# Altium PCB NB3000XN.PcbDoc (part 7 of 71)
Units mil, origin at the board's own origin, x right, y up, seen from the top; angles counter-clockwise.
Board outline 9527.56 x 6929.77 mil, 6 copper layers (Top Layer, GND+SHIELD, MidLayer1, MidLayer2, P2 - 3V3+5V0, Bottom Layer), stack 62.375 mil thick; 832 components, 1027 nets, 4655 pads, 4981 vias.
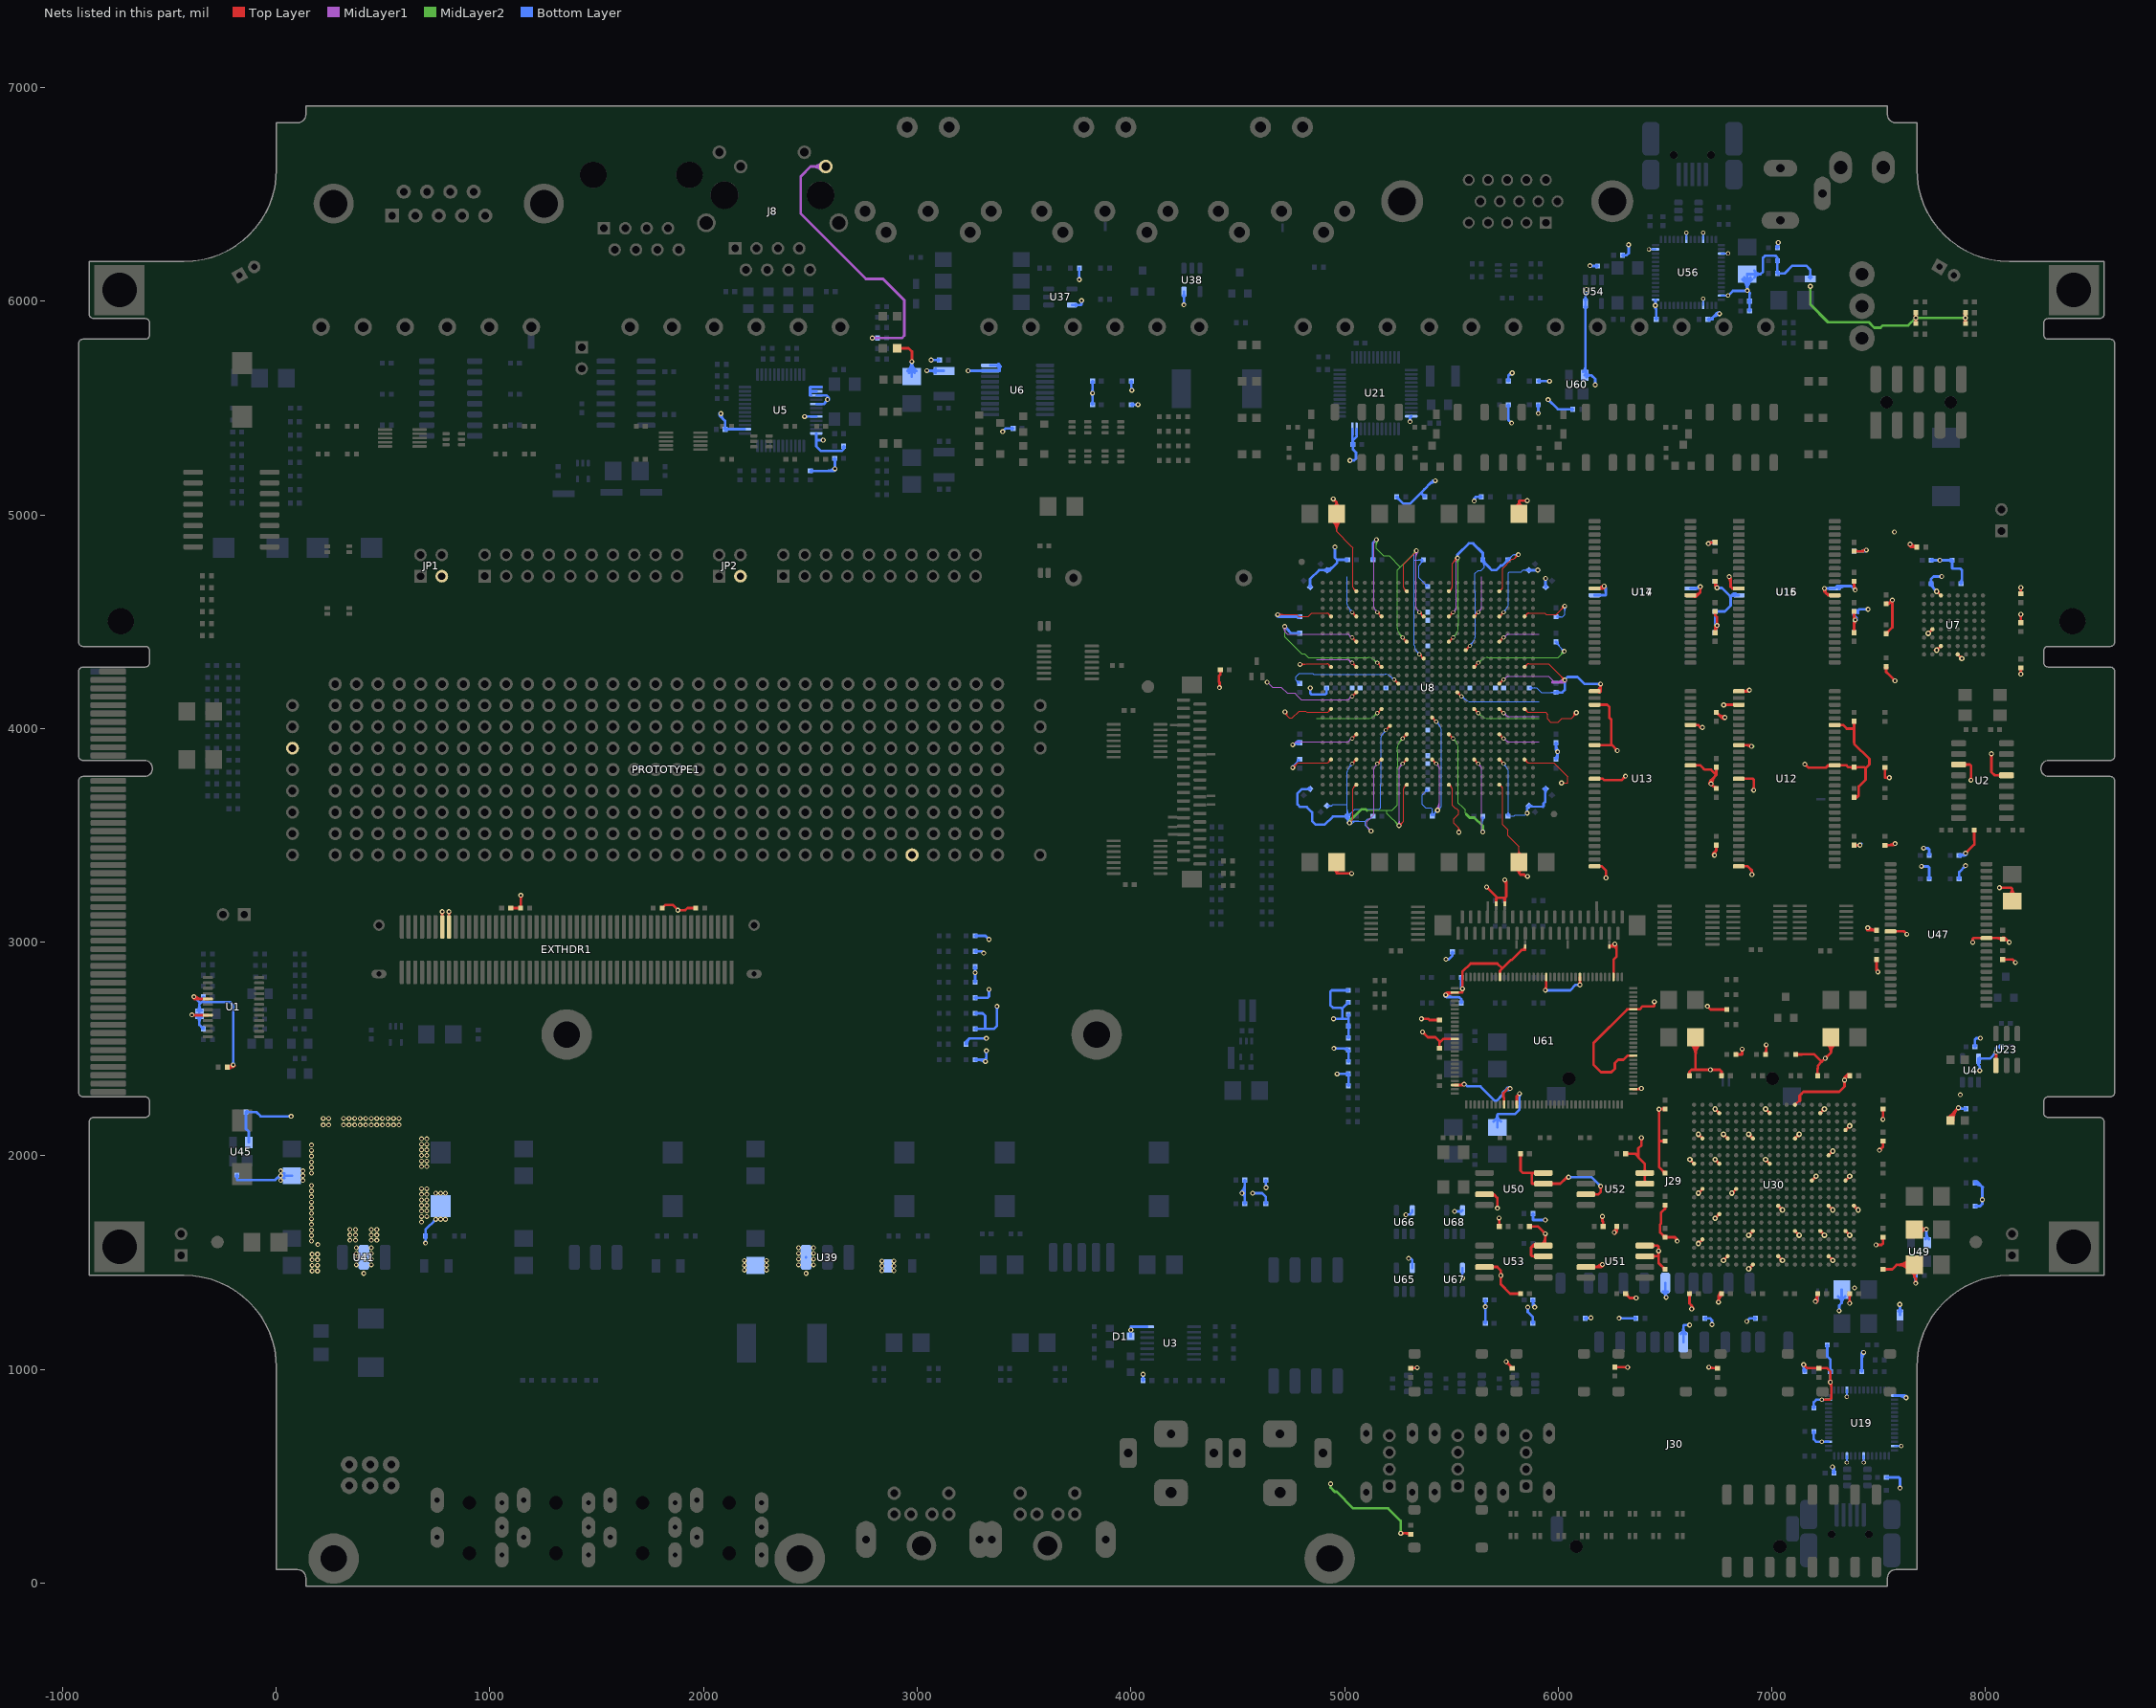
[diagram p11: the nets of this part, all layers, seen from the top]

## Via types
v1: diameter 23, hole 11.81, Top Layer to Bottom Layer, 3672 vias
v2: diameter 26, hole 11.81, Top Layer to Bottom Layer, 461 vias
v3: diameter 19, hole 11.81, Top Layer to Bottom Layer, tented both sides, 396 vias
v4: diameter 23.62, hole 11.81, Top Layer to Bottom Layer, 288 vias
v5: diameter 20, hole 11.81, Top Layer to Bottom Layer, 91 vias
v6: diameter 23, hole 11.81, Top Layer to Bottom Layer, tented both sides, 50 vias
v7: diameter 31, hole 11.81, Top Layer to Bottom Layer, 15 vias
v8: diameter 27.56, hole 11.81, Top Layer to Bottom Layer, tented both sides, 4 vias
v9: diameter 29, hole 11.81, Top Layer to Bottom Layer, 3 vias
v10: diameter 21, hole 11.81, Top Layer to Bottom Layer, 1 vias

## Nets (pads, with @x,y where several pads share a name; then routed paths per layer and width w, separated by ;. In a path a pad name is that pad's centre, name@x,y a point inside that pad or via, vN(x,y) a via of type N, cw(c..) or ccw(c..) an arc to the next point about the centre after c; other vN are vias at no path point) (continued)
3V3: (continued)
  Top Layer w12: v4(-395,2660) -393.62,2658.62 U1.8@-320,2658.62 ; v4@-390.89,2664.11 ccw(c-377.64,2677.36) -377.64,2658.62 ; v1@-389.6,2740.4 ccw(c-374.65,2755.35) -374.65,2734.21 ; v1(-385,2745) -385,2736.23 -382.98,2734.21 U1.5@-320,2734.21 ; v1@-381.11,2748.89 ccw(c-345.68,2784.32) -345.68,2734.21 ; R99.2@-231.27,2409.28 ccw(c-225.51,2423.88) -214.41,2412.78 ; R99.2@-226.86,2420.44 ccw(c-218.18,2442.41) v1(-201.48,2425.71) -212.18,2415 R99.2@-228.82,2415 ccw(c-228.82,2440.67) v1@-206.3,2428.35 ; R99.2@-225.06,2411.24 cw(c-215.98,2402.16) -215.98,2415 cw(c-215.98,2427.84) R99.2@-225.06,2418.76 ; -208.57,2415 ccw(c-208.57,2429.59) v1@-195.77,2422.59 ; v1@772.94,3139.15 cw(c763.18,3129.38) 776.99,3129.38 ; EXTHDR1.87@776.99,3071.85 v1@776.99,3142.88 ; 776.99,3130.14 cw(c789.73,3130.14) v1@780.72,3139.15 ; v1@804.44,3139.15 cw(c794.67,3129.38) 808.49,3129.38 ; EXTHDR1.85@808.49,3071.85 v1@808.49,3142.88 ; 808.49,3130.14 cw(c821.23,3130.14) v1@812.22,3139.15 ; R283.1@1097.74,3160 R234.2@1143.82,3160 1145,3161.18 v1(1145,3220) ; R283.1@1101.51,3156.24 cw(c1110.59,3147.15) 1110.59,3160 cw(c1110.58,3172.83) R283.1@1101.51,3163.76 ; R234.2@1140.06,3156.24 ccw(c1130.98,3147.16) 1130.98,3160 ccw(c1130.98,3172.84) R234.2@1140.06,3163.76 ; v1@1141.11,3216.11 cw(c1131.72,3206.72) 1145,3206.72 cw(c1158.28,3206.72) v1@1148.89,3216.11 ; R277.1@1806.34,3160.02 1821.32,3175 1855.06,3175 v1(1880.02,3150.04) 1915.04,3150.04 1925.03,3160.03 R278.2@1964.34,3160.03 ; LED3.1@2905,5780 2960,5780 2975.19,5764.81 v1(2975.19,5717.71) ; LED3.1@2914.82,5770.47 cw(c2937.36,5748.59) 2937.36,5780 cw(c2937.36,5811.41) LED3.1@2914.82,5789.53 ; v1@2971.3,5721.6 ccw(c2961.91,5730.99) 2975.19,5730.99 ccw(c2988.47,5730.99) v1@2979.08,5721.6 ; v1@4411.3,4195.6 ccw(c4401.91,4204.99) 4415.19,4204.99 ccw(c4428.47,4204.99) v1@4419.08,4195.6 ; v1@4412.02,4194.87 v1(4415.19,4191.71) 4415.19,4216.83 4412.02,4220 4412.02,4245 4418.82,4251.79 R147.1@4418.82,4275 ; R147.1@4415.06,4270.75 cw(c4405.98,4261.67) 4418.82,4261.67 cw(c4431.66,4261.67) R147.1@4422.58,4270.75 ; v1(4947.19,5075.04) 4947.19,5068.37 4948.86,5066.71 4955.52,5066.71 4962.99,5059.24 ; C276.1@4950.02,5039.68 ccw(c4941.77,5059.24) 4962.99,5059.24 ; C278.1@4951.56,3339.71 cw(c4945.6,3323.38) 4962.99,3323.38 ; C278.1@4962.99,3375 4962.99,3323.37 ; C276.1@4962.99,4982.01 C276.1@4962.99,5005 4962.99,5059.24 ; C278.1@4974.42,3339.71 ccw(c4980.38,3323.38) 4962.99,3323.38 ; C276.1@4975.97,5039.68 cw(c4984.22,5059.24) 4962.99,5059.24 ; v1@5029.64,3317.82 ccw(c5020.25,3308.43) 5020.25,3321.71 ccw(c5020.25,3334.99) v1@5029.64,3325.6 ; v1(5033.52,3321.71) 4964.66,3321.71 4962.99,3323.37 ; v1@5266.75,229.49 cw(c5276.14,220.1) 5276.14,233.37 cw(c5276.14,246.65) v1@5266.75,237.26 ; v1@5267.41,228.82 v1(5262.86,233.37) 5305.44,233.37 R107.1@5310,228.82 ; 5285.67,233.37 cw(c5285.67,204.98) R107.1@5305.75,225.06 ; R102.1@5310,1006.18 5338.19,1006.18 5340.19,1008.18 v1(5340.19,1008.37) ; R102.1@5314.25,1002.42 cw(c5323.33,993.34) 5323.33,1006.18 cw(c5323.33,1019.02) R102.1@5314.25,1009.94 ; R102.1@5321.62,1006.18 ccw(c5321.62,1026.95) v1@5336.3,1012.26 ; v1@5360.19,2641.85 5392.19,2641.85 5397.86,2636.18 R273.2@5445,2636.18 ; v1@5364.08,2637.82 cw(c5373.8,2628.09) 5373.8,2641.85 ; v1@5364.08,2645.6 ccw(c5373.13,2654.65) 5373.13,2641.85 ; v4@5365,2574.19 cw(c5365,2560.16) 5374.92,2570.08 cw(c5384.84,2580) v4@5370.81,2580 ; v4(5365,2580) 5389.88,2555.12 5425.12,2555.12 5445,2535.23 ; R273.2@5440.75,2632.42 ccw(c5431.67,2623.34) 5431.67,2636.18 ccw(c5431.67,2649.02) R273.2@5440.75,2639.94 ; R272.2@5441.24,2507.45 ccw(c5432.16,2516.53) 5445,2516.53 ccw(c5457.84,2516.53) R272.2@5448.76,2507.45 ; R272.2@5445,2503.69 5445,2535.23 ; v1@5469.26,2757.3 cw(c5487.14,2739.43) 5487.14,2764.71 ; v1(5473.86,2752.71) 5485.86,2764.71 U61.104@5516.83,2764.71 ; v1@5477.75,2748.82 cw(c5516.11,2710.46) U61.104@5516.11,2764.71 ; U61.126@5516.83,2331.35 5554.88,2331.35 v1@5560,2336.47 ; U61.115@5516.83,2547.88 5463.03,2547.88 5447.69,2532.54 5445,2535.23 ; 5537.9,2331.35 ccw(c5537.9,2357.1) v1@5556.11,2338.89 ; v1@5547.97,2785.93 ccw(c5538.58,2795.32) 5551.86,2795.32 ccw(c5565.14,2795.32) v1@5555.75,2785.93 ; v1(5560,2335) v1@5560,2336.47 ; v1@5560,2340 v1@5560,2336.47 ; U53.3@5655,1480 5715.19,1480 5731.86,1463.33 v1(5731.86,1440.19) 5731.86,1398.62 5775.48,1355 C165.2@5824.33,1355 ; U50.3@5655,1820 5698.52,1820 ; v1@5665.19,3252.87 cw(c5665.19,3239.6) 5674.58,3248.99 cw(c5683.97,3258.37) v1@5670.69,3258.37 ; v1(5665.19,3258.37) 5715.19,3208.37 ; U50.3@5684.53,1824.22 cw(c5684.53,1800.62) 5701.22,1817.31 ; U50.3@5689.37,1813.91 cw(c5696.94,1804.42) 5705.52,1813 ; U53.3@5690.03,1474.5 cw(c5703.31,1461.22) 5703.31,1480 cw(c5703.31,1498.78) U53.3@5690.03,1485.5 ; U50.3@5691.13,1815.89 cw(c5698.52,1811.3) 5698.52,1820 ; U50.3@5691.13,1824.11 ccw(c5698.52,1828.7) 5698.52,1820 ; NT36.2@5710,3180 5710,3203.52 5714.86,3208.37 5715.19,3208.37 ; v1@5711.3,1758.93 ccw(c5701.91,1768.32) 5715.19,1768.32 ccw(c5728.47,1768.32) v1@5719.08,1758.93 ; v1(5715.19,1755.04) 5715.19,1803.33 5698.52,1820 ; v1@5719.64,1705.15 cw(c5708.3,1693.81) 5724.33,1693.81 ; C158.1@5720.22,1674.11 ccw(c5710.3,1684.03) 5724.33,1684.03 ccw(c5738.36,1684.03) C158.1@5728.44,1674.11 ; C158.1@5724.33,1670 v1@5724.33,1709.04 ; U61.94@5727.48,2837.34 5727.48,2866.71 ; 5727.52,2866.71 5738.02,2877.21 ; v1@5727.97,1436.3 cw(c5718.58,1426.92) 5731.86,1426.92 cw(c5745.14,1426.92) v1@5735.75,1436.3 ; v1@5727.97,1444.08 ccw(c5718.58,1453.47) 5731.86,1453.47 ccw(c5745.14,1453.47) v1@5735.75,1444.08 ; v1@5746.3,3287.82 cw(c5720.82,3262.33) 5756.86,3262.33 ; U61.10@5747.17,2240 5747.17,2271.33 5743.5,2275 5743.5,2293.91 5764.97,2315.37 5779.52,2315.37 5779.15,2315 v1(5775,2315) ; NT35.2@5750,3180 5750,3207.18 ; v1(5750.19,3291.71) 5756.86,3285.04 5756.86,3214.04 5750,3207.18 ; v1@5756.5,1031.16 cw(c5756.5,1017.88) 5765.89,1027.27 cw(c5775.28,1036.66) v1@5762,1036.66 ; v1(5756.5,1036.66) 5785,1008.16 R103.1@5785,1006.18 ; 5773.68,1019.48 cw(c5760.38,1006.18) R103.1@5779.19,1006.18 ; C277.1@5801.08,5038.26 ccw(c5786.53,5065.04) 5817.01,5065.04 ; C279.1@5805.37,3339.79 cw(c5799.14,3323.04) 5817.01,3323.04 ; U61.13@5806.22,2240 5806.22,2278.74 v1(5819.19,2291.71) ; C279.1@5817.01,3375 5817.01,3323.04 ; C277.1@5817.01,5005 5817.01,5065.04 ; C165.2@5820.22,1350.89 ccw(c5810.3,1340.97) 5810.3,1355 ccw(c5810.3,1369.03) C165.2@5820.22,1359.11 ; C159.2@5820.22,2005.89 cw(c5810.3,1995.97) 5824.33,1995.97 cw(c5838.36,1995.97) C159.2@5828.44,2005.89 ; C159.2@5824.33,2010 5824.33,1930.67 5835,1920 5874.19,1920 ; C279.1@5828.64,3339.79 ccw(c5834.88,3323.04) 5817.01,3323.04 ; C277.1@5832.94,5038.26 cw(c5847.48,5065.04) 5817.01,5065.04 ; NT37.2@5845,2975.5 cw(c5828.52,2980.84) 5828.52,2963.52 ; NT37.2@5845,2980 5845,2965 5843.52,2963.52 5828.52,2963.52 ; v1@5848.52,3308.37 5840.52,3316.37 5823.67,3316.37 5817.01,3323.04 ; v1@5851.3,5062.82 ccw(c5841.91,5053.43) 5841.91,5066.71 ccw(c5841.91,5079.99) v1@5851.3,5070.6 ; v1(5855.19,5066.71) 5818.67,5066.71 5817.01,5065.04 ; C164.1@5865.67,1670 5905.19,1670 v1(5940,1635.19) v1@5940,1630.04 ; C164.1@5869.78,1665.89 cw(c5879.7,1655.97) 5879.7,1670 cw(c5879.7,1684.03) C164.1@5869.78,1674.11 ; 5872.25,1570.4 cw(c5886.52,1556.13) U53.8@5897.01,1573.36 ; 5879.39,1577.53 cw(c5896.69,1560.24) U53.8@5901.98,1584.12 ; 5883.04,1581.19 cw(c5894.69,1569.54) U53.8@5903.26,1583.6 ; U53.7@5895.56,1524.5 ccw(c5882.28,1511.22) 5882.28,1530 ccw(c5882.28,1548.78) U53.7@5895.56,1535.5 ; U53.8@5895.56,1574.5 ccw(c5882.28,1561.22) 5882.28,1580 ccw(c5882.28,1598.78) U53.8@5895.56,1585.5 ; U50.7@5895.56,1864.5 ccw(c5882.28,1851.22) 5882.28,1870 ccw(c5882.28,1888.78) U50.7@5895.56,1875.5 ; U50.8@5895.56,1914.5 ccw(c5882.28,1901.22) 5882.28,1920 ccw(c5882.28,1938.78) U50.8@5895.56,1925.5 ; U53.8@5925.09,1585.5 ccw(c5889.09,1621.5) 5940,1621.5 ; U53.8@5930,1580 5930.3,1580.3 U53.8@5930.59,1580.59 ; U53.7@5930.59,1530 5877.9,1530 5873.52,1534.37 5873.52,1571.67 5881.86,1580 U53.8@5930.59,1580 U53.8@5930.59,1580.59 ; U50.8@5930.59,1920 5874.19,1920 ; U53.8@5933.57,1577.02 ccw(c5918.06,1592.53) U53.8@5940,1592.53 ; v1@5934.5,1635.19 ccw(c5921.22,1635.19) 5930.61,1644.58 ccw(c5940,1653.97) v1@5940,1640.69 ; v1@5936.11,1631.3 cw(c5926.72,1621.92) 5940,1621.92 cw(c5953.28,1621.92) v1@5943.89,1631.3 ; v1@5936.3,2778.93 ccw(c5917.68,2797.55) 5944.02,2797.55 ; v1@5939.92,1630.04 v1@5940,1630.04 ; v1@5940.19,1695.96 v1@5940.19,1696.04 ; v1(5940.19,2775.04) 5944.02,2778.87 U61.83@5944.01,2837.34 ; v1(5952.77,5540) v1@5958.3,5540 ; U50.7@5965.62,1864.5 cw(c5978.9,1851.22) 5978.9,1870 cw(c5978.9,1888.78) U50.7@5965.62,1875.5 ; 6024.91,1884.76 cw(c6048.52,1861.14) v1@6048.52,1894.54 ; v1(6048.52,1900.04) 6040.19,1900.04 6010.23,1870.08 6010.23,1870 U50.7@5930.59,1870 5878.86,1870 5877.19,1871.67 5877.19,1917 5874.19,1920 ; v1@6097.97,2804.6 ccw(c6089.45,2813.11) 6101.49,2813.11 ; 6101.49,2814.86 ccw(c6116.01,2814.86) v1@6105.75,2804.6 ; U61.75@6101.49,2837.34 6101.49,2801.07 v1(6101.86,2800.71) ; U51.3@6130,1480 6202.48,1480 6206.86,1484.37 v1(6206.86,1491.71) ; U52.3@6130,1820 6188.15,1820 6198.52,1830.37 v1(6198.52,1858.37) ; U51.3@6165.03,1474.5 cw(c6178.31,1461.22) 6178.31,1480 cw(c6178.31,1498.78) U51.3@6165.03,1485.5 ; U52.3@6165.03,1814.5 cw(c6178.31,1801.22) 6178.31,1820 cw(c6178.31,1838.78) U52.3@6165.03,1825.5 ; U51.3@6165.31,1480 ccw(c6165.31,1533.25) v1@6202.97,1495.6 ; U13.27@6170.59,3355.55 6204.19,3355.55 6223.52,3336.22 v1(6223.52,3301.04) ; U13.14@6170.59,3765 6208.56,3765 6215.19,3758.37 6296.19,3758.37 v1(6315.19,3777.37) ; U13.9@6170.59,3922.48 6251.08,3922.48 ; U13.3@6170.59,4111.46 6228.77,4111.46 6240.19,4100.04 6240.19,4050.04 6248.52,4041.71 6248.52,3925.04 6251.08,3922.48 ; U13.1@6170.59,4174.45 6199.45,4174.45 ; U17.11@6170.59,4655.75 6204.23,4655.75 v1(6215.19,4666.71) ; U17.11@6175.45,4655.75 ccw(c6175.45,4706.45) v1@6211.3,4670.6 ; U13.1@6185.37,4177.32 ccw(c6155.31,4208.37) v1(6198.52,4208.37) ; U13.1@6185.56,4177.5 ccw(c6160.21,4207.45) v1@6199.45,4207.45 ; U13.1@6193.32,4168.34 ccw(c6182.12,4181.57) 6199.45,4181.57 ; U13.1@6193.71,4168.7 ccw(c6182.72,4180.05) 6198.52,4180.05 ; 6194.28,1480 ccw(c6194.28,1504.28) v1@6211.45,1487.11 ; v1@6194.64,1854.49 cw(c6185.25,1845.1) 6198.52,1845.1 cw(c6211.8,1845.1) v1@6202.41,1854.49 ; 6199.45,4192.86 ccw(c6183.01,4192.86) 6194.64,4204.49 cw(c6185.25,4195.1) 6198.52,4195.1 cw(c6211.8,4195.1) v1@6202.41,4204.49 ; v1@6202.97,1712.82 cw(c6193.58,1703.43) 6206.86,1703.43 cw(c6220.14,1703.43) v1@6210.75,1712.82 ; 6204.42,4655.75 ccw(c6204.42,4677.48) v1@6219.79,4662.11 ; C160.1@6206.56,1674.11 ccw(c6196.64,1684.03) 6210.67,1684.03 ccw(c6224.7,1684.03) C160.1@6214.78,1674.11 ; v1(6206.86,1716.71) 6206.86,1694.04 6207,1694.04 6210.67,1690.37 C160.1@6210.67,1670 ; v1@6219.64,3304.93 ccw(c6210.25,3314.32) 6223.52,3314.32 ccw(c6236.8,3314.32) v1@6227.41,3304.93 ; 6257.57,2980 ccw(c6257.57,2994.68) v1@6271.25,2989.34 ; U61.67@6258.97,2837.34 6258.98,2918.83 6273.52,2933.37 6273.52,2983.37 v1(6265.19,2991.71) 6265.19,2983.37 6261.82,2980 NT34.2@6240,2980 ccw(c6240,3001.54) v1@6260.07,2993.71 ; v1@6260.02,1646.6 ccw(c6248.05,1670) C163.2@6274.33,1670 ; v1@6261.3,2987.82 cw(c6231.79,2958.31) 6273.52,2958.31 ; R104.2@6265,1011.18 v1@6331.18,1011.18 ; v1@6265.48,1635.92 ccw(c6258.09,1650.38) 6274.33,1650.38 ; v1@6266.71,1641.71 v1(6262.52,1641.71) 6274.33,1653.51 C163.2@6274.33,1670 ; R104.2@6269.25,1007.42 cw(c6278.33,998.34) 6278.33,1011.18 cw(c6278.33,1024.02) R104.2@6269.25,1014.94 ; C163.2@6270.22,1665.89 cw(c6260.3,1655.97) 6274.33,1655.97 cw(c6288.36,1655.97) C163.2@6278.44,1665.89 ; v1@6271.36,3896.71 ccw(c6258.08,3896.71) 6267.47,3906.1 ccw(c6276.86,3915.49) v1@6276.86,3902.21 ; v1(6276.86,3896.71) 6251.08,3922.48 ; 6308.87,1011.18 cw(c6308.87,993.87) v1@6321.11,1006.11 ; v1@6309.69,3777.37 cw(c6296.41,3777.37) 6305.8,3767.99 cw(c6315.19,3758.6) v1@6315.19,3771.87 ; C161.2@6315.67,1349.19 cw(c6315.67,1335.16) 6325.59,1345.08 cw(c6335.51,1355) C161.2@6321.48,1355 ; C161.2@6315.67,1355 6335.67,1335 v4(6365,1335) ; C162.1@6315.67,2010 6361.52,2010 6375.07,1996.45 ; C162.1@6319.78,2005.89 cw(c6329.7,1995.97) 6329.7,2010 cw(c6329.7,2024.03) C162.1@6319.78,2014.11 ; U61.48@6351.71,2469.14 6324.96,2469.14 6305.86,2450.04 6281.86,2450.04 6265.19,2433.37 6265.19,2408.37 6248.52,2391.71 6200.52,2391.71 6165.19,2427.04 6165.19,2527.16 6323.71,2685.68 U61.59@6351.93,2685.68 6380.86,2685.68 6395.22,2700.04 6448.19,2700.04 6449.86,2701.71 v1(6449.86,2721.37) ; U61.40@6351.93,2311.66 v1@6385.86,2311.66 ; v4@6360.89,1330.89 ccw(c6350.97,1320.97) 6350.97,1335 ccw(c6350.97,1349.03) v4@6360.89,1339.11 ; U61.40@6367.28,2311.66 ccw(c6367.28,2337.62) v1@6385.64,2319.26 ; U52.7@6373.52,1870 U52.7@6405.59,1870 U52.8@6405.59,1920 6405.59,1962.57 6375.07,1993.08 6375.07,1996.45 ; v4@6385.89,2080.89 cw(c6375.91,2070.91) 6390.02,2070.91 ; v1@6385.86,2311.71 v1(6389.52,2315.37) ; 6390.02,2071.03 cw(c6403.97,2071.03) v4@6394.11,2080.89 ; v4(6390,2085) 6390,2075.64 6390.02,2050.21 6390.19,2050.04 6375.07,2034.93 6375.07,1996.45 ; U52.7@6400.09,1875.5 ccw(c6386.81,1888.78) 6405.59,1888.78 ccw(c6424.37,1888.78) U52.7@6411.09,1875.5 ; U52.8@6400.09,1914.5 cw(c6386.81,1901.22) 6405.59,1901.22 cw(c6424.37,1901.22) U52.8@6411.09,1914.5 ; U52.8@6400.09,1925.5 ccw(c6386.81,1938.78) 6405.59,1938.78 ccw(c6424.37,1938.78) U52.8@6411.09,1925.5 ; U51.7@6405.59,1530 6470,1530 ; U51.8@6405.59,1580 6465,1580 6470,1575 v1(6470,1555) ; U51.7@6440.62,1524.5 cw(c6453.9,1511.22) 6453.9,1530 cw(c6453.9,1548.78) U51.7@6440.62,1535.5 ; U51.8@6440.62,1574.5 cw(c6453.9,1561.22) 6453.9,1580 cw(c6453.9,1598.78) U51.8@6440.62,1585.5 ; v1@6445.97,2717.49 cw(c6436.58,2708.1) 6449.86,2708.1 cw(c6463.14,2708.1) v1@6453.75,2717.49 ; v1@6466.11,1551.11 cw(c6456.72,1541.72) 6470,1541.72 cw(c6483.28,1541.72) v1@6473.89,1551.11 ; v1@6466.11,1558.89 ccw(c6456.72,1568.28) 6470,1568.28 ccw(c6483.28,1568.28) v1@6473.89,1558.89 ; v1@6467.97,2214.49 cw(c6458.58,2205.1) 6471.86,2205.1 cw(c6485.14,2205.1) 6475.75,2214.49 cw(c6487.44,2202.79) 6487.44,2219.33 ; v1@6471.23,1555 v1(6470,1555) ; v1(6471.86,2218.37) 6471.86,2069.33 ; v1@6473.52,1552.71 v1@6473.52,1555 ; v1@6473.62,1551.38 v1(6470,1555) ; v1@6474.48,2219.33 C224.1@6500,2219.33 ; C242.1@6494.19,1469.33 ccw(c6480.16,1469.33) 6490.08,1479.25 ccw(c6500,1489.17) C242.1@6500,1475.14 ; C246.1@6494.19,1619.33 ccw(c6480.16,1619.33) 6490.08,1629.25 ccw(c6500,1639.17) C246.1@6500,1625.14 ; C245.1@6494.19,1919.33 ccw(c6480.16,1919.33) 6490.08,1929.25 ccw(c6500,1939.17) C245.1@6500,1925.14 ; C241.1@6495.89,1765.22 cw(c6485.97,1755.3) 6500,1755.3 cw(c6514.03,1755.3) C241.1@6504.11,1765.22 ; C240.1@6495.89,2065.22 ccw(c6485.97,2055.3) 6485.97,2069.33 ccw(c6485.97,2083.36) C240.1@6495.89,2073.44 ; C224.1@6495.89,2215.22 ccw(c6485.97,2205.3) 6485.97,2219.33 ccw(c6485.97,2233.36) C224.1@6495.89,2223.44 ; C245.1@6499.96,1919.37 6471.86,1947.47 6471.86,2069.33 ; C242.1@6500,1469.33 6470,1499.33 6470,1530 ; C241.1@6500,1769.33 6500,1752.71 6498.67,1751.37 6498.52,1751.37 6481.86,1734.71 6481.86,1683.37 6477.52,1679.04 6477.52,1641.71 6477.62,1641.71 C246.1@6500,1619.33 6543.48,1619.33 6543.48,1619.04 6545.81,1616.71 6549.52,1616.71 6557.19,1609.04 v1(6557.19,1600.71) ; C240.1@6500,2069.33 6471.86,2069.33 ; C246.1@6504.11,1615.22 cw(c6514.03,1605.3) 6514.03,1619.33 cw(c6514.03,1633.36) C246.1@6504.11,1623.44 ; v1@6505.1,1337.61 v1@6505.19,1337.52 ; v1@6505.19,1337.37 v1@6505.19,1337.52 ; v1(6505.19,1337.71) v1@6505.19,1337.52 ; 6545.36,1620.87 cw(c6529.33,1604.85) v1@6551.75,1601.52 ; C221.1@6610.22,1350.89 cw(c6600.3,1340.97) 6614.33,1340.97 cw(c6628.36,1340.97) C221.1@6618.44,1350.89 ; C215.1@6610.22,2379.11 ccw(c6600.3,2389.03) 6614.33,2389.03 ccw(c6628.36,2389.03) C215.1@6618.44,2379.11 ; C221.1@6614.33,1355 6614.33,1309.23 6624.52,1299.04 v1(6624.52,1283.37) ; C215.1@6614.33,2375 6614.33,2393.9 6623.33,2402.9 6645,2402.9 ; C202.1@6619.4,2527.47 cw(c6562.43,2470.5) 6642.99,2470.5 cw(c6723.55,2470.5) C202.1@6666.59,2527.47 ; U13.43@6619.41,3827.99 6665.19,3827.99 6681.86,3811.32 6681.86,3811.04 6684.52,3808.37 6715.19,3808.37 6715.19,3807.99 6740,3783.18 ; U13.49@6619.41,4016.97 6654.52,4016.97 6666.49,4005 v1(6675,4005) v1@6670.15,4005 ; U17.33@6619.41,4624.25 6652.07,4624.25 6665.19,4637.37 ; 6625.22,1298.35 cw(c6611.13,1284.26) v1@6631.01,1282.95 ; C202.1@6627.88,2535.95 cw(c6591.4,2499.47) 6642.99,2499.47 cw(c6694.58,2499.47) C202.1@6658.1,2535.95 ; U17.33@6635.81,4616.34 ccw(c6637.93,4630.83) 6648.29,4620.47 ; U17.33@6637.55,4628.21 ccw(c6642.24,4660.32) 6665.19,4637.37 ; C202.1@6642.99,2555 6642.99,2404.91 6645,2402.9 ; v1@6661.3,4660.15 cw(c6651.91,4650.76) 6665.19,4650.76 cw(c6678.47,4650.76) v1@6669.08,4660.15 ; v1(6665.19,4664.04) 6665.19,4637.37 ; v1(6698.52,2700.04) 6713.56,2685 R215.1@6788.82,2685 ; v1(6702.52,4865.71) 6708.19,4871.38 C79.1@6735,4871.38 ; v1(6704.52,1010.71) 6706.86,1010.71 6705.69,1009.54 6702.33,1006.18 6704.52,1006.18 R105.1@6745,1006.18 ; v1@6706.41,4861.82 cw(c6729.49,4838.75) C79.1@6729.49,4871.38 ; v1@6708.41,1014.6 ccw(c6728.73,1034.92) 6728.73,1006.18 ; v1@6708.49,2399.01 ccw(c6699.1,2389.62) 6699.1,2402.9 ccw(c6699.1,2416.18) v1@6708.49,2406.79 ; v1@6708.69,3741.71 cw(c6733.24,3741.71) 6715.88,3759.06 ; v1@6711.3,3745.6 ccw(c6701.91,3754.99) 6715.19,3754.99 ccw(c6728.47,3754.99) v1@6719.08,3745.6 ; v1@6715.19,3736.21 cw(c6715.19,3722.93) 6724.58,3732.32 cw(c6733.97,3741.71) 6720.69,3741.71 cw(c6774.21,3741.71) 6736.37,3779.55 ; v1@6716.27,2399.01 cw(c6725.66,2389.62) 6725.66,2402.9 cw(c6725.66,2416.18) v1@6716.27,2406.79 ; 6725.73,3731.17 ccw(c6740,3745.45) C67.1@6740,3725.26 ; v1@6726.07,3404.09 cw(c6736.99,3409.65) 6728.32,3418.32 ; C84.1@6730.89,4453.36 ccw(c6720.97,4463.29) 6735,4463.29 ccw(c6749.03,4463.28) C84.1@6739.11,4453.36 ; C83.1@6730.89,4544.51 cw(c6720.97,4534.59) 6735,4534.59 cw(c6749.03,4534.6) C83.1@6739.11,4544.51 ; C80.1@6730.89,4685.22 cw(c6720.97,4675.3) 6735,4675.3 cw(c6749.03,4675.3) C80.1@6739.11,4685.22 ; C79.1@6730.89,4867.27 ccw(c6720.97,4857.35) 6720.97,4871.38 ccw(c6720.97,4885.41) C79.1@6730.89,4875.49 ; v1(6731.86,3407.04) 6731.86,3421.86 6740,3430 ; C84.1@6735,4449.26 v1@6735,4480.23 ; C84.1@6735,4449.99 cw(c6776.24,4449.99) v1@6747.08,4479.15 ; C83.1@6735,4548.62 6735,4530.04 6743.19,4521.85 v1(6743.19,4483.04) ; C68.1@6735.89,3450.07 cw(c6725.97,3440.15) 6740,3440.15 cw(c6754.03,3440.15) C68.1@6744.11,3450.07 ; C66.1@6735.89,3814.71 cw(c6725.97,3804.79) 6740,3804.79 cw(c6754.03,3804.79) C66.1@6744.11,3814.71 ; v1@6736.76,3409.54 cw(c6752.46,3417.54) 6740,3430 ; v1@6739.3,4486.93 ccw(c6729.91,4496.32) 6743.19,4496.32 ccw(c6756.47,4496.32) v1@6747.08,4486.93 ; C68.1@6740,3454.18 6740,3430 ; C67.1@6740,3719.45 6737.45,3719.45 v1(6715.19,3741.71) 6715.19,3758.37 6740,3783.18 ; C66.1@6740,3818.82 6740,3783.18 ; C65.1@6740,4070.01 cw(c6740,4055.98) 6749.92,4065.9 cw(c6759.84,4075.82) C65.1@6745.81,4075.82 ; C65.1@6740,4075.82 6763.45,4052.37 v1(6780.52,4052.37) ; R105.1@6740.75,1002.42 ccw(c6731.67,993.34) 6731.67,1006.18 ccw(c6731.67,1019.02) R105.1@6740.75,1009.94 ; v1(6743.19,4658.37) 6735,4666.56 C80.1@6735,4689.33 ccw(c6771.34,4689.33) v1@6746.89,4662.44 ; v1@6746.11,1318.89 ccw(c6736.72,1328.28) 6750,1328.28 ccw(c6763.28,1328.28) v1@6753.89,1318.89 ; C65.1@6748.54,4067.29 ccw(c6772.99,4091.73) v1@6779.49,4057.78 ; v1@6750,1312.51 cw(c6799.07,1312.51) C237.1@6768.01,1350.5 ; v1(6750,1315) 6750,1340.67 C237.1@6764.33,1355 ; 6750,1334.73 cw(c6764.46,1334.73) C237.1@6764.37,1349.19 ; 6750,1337.83 cw(c6778.37,1337.83) C237.1@6760.41,1359.79 ; C237.1@6758.52,1355 cw(c6744.49,1355) 6754.41,1345.08 cw(c6764.33,1335.16) C237.1@6764.33,1349.19 ; C231.1@6760.22,2379.11 ccw(c6750.3,2389.03) 6764.33,2389.03 ccw(c6778.36,2389.03) C231.1@6768.44,2379.11 ; C231.1@6764.33,2375 6764.33,2395 6756.43,2402.9 v1(6712.38,2402.9) 6645,2402.9 ; 6764.55,4051.27 ccw(c6778.13,4064.86) v1@6781.75,4045.99 ; v4(6775,4110) 6776.46,4111.46 U12.3@6845.59,4111.46 ; v1@6776.64,4048.49 ccw(c6767.25,4039.1) 6767.25,4052.37 ccw(c6767.25,4065.65) v1@6776.64,4056.26 ; v4@6779.11,4105.89 cw(c6792.55,4092.45) 6792.55,4111.46 ; R215.1@6785.06,2681.24 ccw(c6775.98,2672.16) 6775.98,2685 ccw(c6775.98,2697.84) R215.1@6785.06,2688.76 ; v1@6796.64,4707.49 cw(c6771.96,4682.81) 6806.86,4682.81 ; v1(6800.52,4711.37) 6806.86,4705.04 6806.86,4664.08 6815.19,4655.75 U16.11@6845.59,4655.75 ; R264.2@6831.18,2475 6860,2475 6861.19,2476.19 v1(6861.19,2500.04) v1@6866.19,2500.04 ; R264.2@6834.94,2471.24 cw(c6844.02,2462.16) 6844.02,2475 cw(c6844.02,2487.84) R264.2@6834.94,2478.76 ; U12.27@6845.59,3355.55 6886.86,3355.55 6892.37,3350.04 6892.52,3350.04 6906.86,3335.71 v1(6906.86,3316.71) ; U12.14@6845.59,3765 6909.9,3765 6915.19,3759.71 v1(6915.19,3711.37) ; U12.9@6845.59,3922.48 6899.42,3922.48 v1(6905.19,3916.71) ; U12.1@6845.59,4174.45 6894.45,4174.45 6895,4175 v4(6895,4180) ; v1@6857.3,2496.15 cw(c6847.91,2486.76) 6861.19,2486.76 cw(c6874.47,2486.76) v1@6865.08,2496.15 ; U12.1@6867.57,4174.45 ccw(c6867.57,4207.43) v4@6890.89,4184.11 ; 6877.98,3922.48 cw(c6877.98,3889.49) v1@6901.3,3912.82 ; v1@6902.97,3320.6 ccw(c6893.58,3329.99) 6906.86,3329.99 ccw(c6920.14,3329.99) v1@6910.75,3320.6 ; v1@6911.3,3715.26 ccw(c6901.91,3724.65) 6915.19,3724.65 ccw(c6928.47,3724.65) v1@6919.08,3715.26 ; R265.2@6967.42,2479.25 ccw(c6952.68,2493.99) 6973.52,2493.99 ; v1@6969.64,2515.82 cw(c6960.25,2506.43) 6973.52,2506.43 cw(c6986.8,2506.43) v1@6977.41,2515.82 ; R265.2@6971.18,2475 6973.52,2477.34 v1(6973.52,2519.71) ; R266.2@7111.18,2475 7140.19,2475 7198.52,2475.04 7233.52,2440.04 ; R266.2@7114.94,2471.24 cw(c7124.02,2462.16) 7124.02,2475 cw(c7124.02,2487.84) R266.2@7114.94,2478.76 ; 7140.19,2291.71 7131.86,2283.37 7131.86,2258.69 7130.54,2258.69 ; v1@7148.52,1017.21 cw(c7148.52,1003.93) 7157.91,1013.32 cw(c7167.3,1022.71) v1@7154.02,1022.71 ; v1(7148.52,1022.71) 7165.05,1006.18 R106.2@7220,1006.18 7258.82,1006.18 7273.52,991.48 v1(7273.52,940.71) v1@7278.52,935.71 ; v1@7154.52,3827.87 cw(c7154.52,3814.6) 7163.91,3823.99 cw(c7173.3,3833.37) v1@7160.02,3833.37 ; v1(7154.52,3833.37) 7171.19,3816.71 7252.19,3816.71 7259.86,3824.37 7259.86,3824.66 7263.19,3827.99 U12.43@7294.41,3827.99 7349.52,3827.99 7358.52,3818.99 7358.52,3818.82 C64.1@7385,3818.82 7433.19,3818.82 7438.52,3813.48 ; v1@7199.84,1322.46 ccw(c7170.55,1355) C223.1@7214.33,1355 ; v1@7207.87,1313.54 ccw(c7194.82,1328.05) 7214.33,1328.05 ; C223.1@7210.22,1350.89 cw(c7200.3,1340.97) 7214.33,1340.97 cw(c7228.36,1340.97) C223.1@7218.44,1350.89 ; C217.1@7210.22,2379.11 ccw(c7200.3,2389.03) 7214.33,2389.03 ccw(c7228.36,2389.03) C217.1@7218.44,2379.11 ; v1@7214.33,1318.37 C223.1@7214.33,1355 ; C217.1@7214.33,2375 7214.33,2407.51 7215.19,2408.37 7215.19,2421.71 ; R106.2@7215.75,1002.42 ccw(c7206.67,993.34) 7206.67,1006.18 ccw(c7206.67,1019.02) R106.2@7215.75,1009.94 ; R106.2@7224.25,1002.42 cw(c7233.33,993.34) 7233.33,1006.18 cw(c7233.33,1019.02) R106.2@7224.25,1009.94 ; v5(7234.34,858.27) 7270.19,858.27 7278.52,866.6 v1@7278.52,935.71 ; v1(7246.19,4655.71) 7246.19,4641.58 7263.52,4624.25 U16.33@7294.41,4624.25 ; v1@7250.19,2462.21 ccw(c7250.19,2475.49) 7259.58,2466.1 ccw(c7268.97,2456.71) v1@7255.69,2456.71 ; v1@7251.37,4653.87 ccw(c7271.76,4646.62) 7256.46,4631.31 ; 7252.85,4634.92 ccw(c7270.6,4652.66) U16.33@7275.99,4628.16 ; 7256.36,3821.16 cw(c7268.02,3809.5) U12.43@7275.13,3824.38 ; C201.1@7256.74,2524.56 cw(c7225.35,2483.53) 7277.01,2483.53 ; C201.1@7264.03,2534.09 cw(c7243.93,2507.81) 7277.01,2507.81 cw(c7310.09,2507.81) C201.1@7289.99,2534.09 ; v1@7269.64,936.82 cw(c7248.17,915.36) 7278.52,915.36 ; v1@7269.64,944.6 ccw(c7260.25,953.99) 7273.52,953.99 ccw(c7286.8,953.99) v1@7277.41,944.6 ; C201.1@7277.01,2555 7277.01,2483.52 ; v1@7278.52,940.71 v1@7278.52,935.71 ; U12.49@7294.41,4016.97 7333.37,4016.97 7350.37,3999.97 7350.37,3999.86 7385,3999.86 ; C201.1@7297.28,2524.56 ccw(c7328.66,2483.53) 7277.01,2483.53 ; v1@7336.11,2351.11 cw(c7326.26,2341.26) 7340.19,2341.26 ; 7340.19,2342.18 cw(c7352.82,2342.18) v1@7343.89,2351.11 ; 7340.62,2367.1 cw(c7352.92,2354.8) C233.1@7361.47,2369.94 ; v1@7345.06,2357.15 cw(c7360.01,2363.51) 7348.52,2375 ; 7349.34,2375.82 cw(c7362.6,2362.55) C233.1@7365.18,2381.13 ; 7351.79,2378.26 cw(c7360.98,2369.07) C233.1@7367.38,2380.39 ; C239.1@7360.22,1350.89 cw(c7350.3,1340.97) 7364.33,1340.97 cw(c7378.36,1340.97) C239.1@7368.44,1350.89 ; C233.1@7360.22,2370.89 ccw(c7350.3,2360.97) 7350.3,2375 ccw(c7350.3,2389.03) C233.1@7360.22,2379.11 ; v1@7360.44,1313.74 ccw(c7351.05,1323.13) 7364.33,1323.13 ccw(c7377.61,1323.13) v1@7368.22,1313.74 ; v1(7364.33,1309.85) C239.1@7364.33,1355 ; C233.1@7364.33,2375 7348.52,2375 7340.19,2366.67 7340.19,2355 7340.19,2325.04 7315.19,2300.04 7148.44,2300.04 7128.11,2279.71 7128.11,2261.12 7130.54,2258.69 ; C64.1@7380.89,3814.71 ccw(c7370.97,3804.79) 7370.97,3818.82 ccw(c7370.97,3832.85) C64.1@7380.89,3822.93 ; C69.1@7380.89,4030.38 cw(c7370.97,4020.46) 7385,4020.46 cw(c7399.03,4020.46) C69.1@7389.11,4030.38 ; C81.1@7380.89,4453.36 ccw(c7370.97,4463.29) 7385,4463.29 ccw(c7399.03,4463.28) C81.1@7389.11,4453.36 ; C86.1@7380.89,4544.51 cw(c7370.97,4534.59) 7385,4534.59 cw(c7399.03,4534.6) C86.1@7389.11,4544.51 ; C85.1@7380.89,4685.22 cw(c7370.97,4675.3) 7385,4675.3 cw(c7399.03,4675.3) C85.1@7389.11,4685.22 ; C70.1@7385,3454.18 7406.86,3454.18 7406.86,3454.37 v1(7412.52,3454.37) ; C63.1@7385,3678.11 7398.52,3678.11 ; C69.1@7385,4034.48 7385,3999.86 ; C81.1@7385,4449.26 7385,4495.18 7390.19,4500.37 v1(7390.19,4508.71) 7385,4513.9 C86.1@7385,4548.62 ; 7385,4482.9 cw(c7416,4482.9) v1@7394.08,4504.82 ; 7385,4534.52 ccw(c7416,4534.52) v1@7394.08,4512.6 ; 7385,4674.18 ccw(c7416,4674.18) v1@7394.08,4652.26 ; C85.1@7385,4689.33 7385,4661.71 7385.19,4661.71 7390.19,4656.71 v1(7390.19,4648.37) ; C82.1@7385,4830.04 7428.19,4830.04 7433.86,4835.71 v1(7442.52,4835.71) ; C63.1@7387.6,3683.31 ccw(c7395.05,3698.25) 7406.86,3686.44 ; C70.1@7389.11,3450.07 cw(c7399.03,3440.15) 7399.03,3454.18 cw(c7399.03,3468.21) C70.1@7389.11,3458.29 ; C64.1@7389.11,3814.71 cw(c7399.03,3804.79) 7399.03,3818.82 cw(c7399.03,3832.85) C64.1@7389.11,3822.93 ; C82.1@7389.11,4825.93 cw(c7399.03,4816.01) 7399.03,4830.04 cw(c7399.03,4844.07) C82.1@7389.11,4834.15 ; C63.1@7389.22,3674.11 cw(c7398.52,3665.28) 7398.52,3678.11 ; C63.1@7389.22,3682.11 ccw(c7398.52,3690.94) 7398.52,3678.11 ; 7398.77,3454.18 ccw(c7398.77,3468.13) v1@7408.64,3458.26 ; 7399.73,3454.18 cw(c7399.73,3441.58) v1@7408.64,3450.49 ; 7415.55,4830.04 ccw(c7415.55,4862.68) v1@7438.64,4839.6 ; v1@7443.92,3062.78 ccw(c7461.07,3079.9) 7461.07,3055.67 ; v1(7448.52,3067.37) 7448.52,3057.71 7446.48,3055.67 7448.52,3055.67 C156.1@7490,3055.67 ; v1@7452.42,3071.26 ccw(c7490,3108.76) C156.1@7490,3055.67 ; 7456.75,3841.71 7456.86,3841.71 ; C155.1@7485.89,2915.22 cw(c7475.97,2905.3) 7490,2905.3 cw(c7504.03,2905.3) C155.1@7494.11,2915.22 ; C156.1@7485.89,3051.56 ccw(c7475.97,3041.64) 7475.97,3055.67 ccw(c7475.97,3069.7) C156.1@7485.89,3059.78 ; 7490,2889.4 ccw(c7525.55,2889.4) v1@7500.41,2864.26 ; C155.1@7490,2919.33 7490,2866.9 v1(7496.52,2860.37) ; v1@7491.41,1579.49 cw(c7500.8,1570.1) 7500.8,1583.37 cw(c7500.8,1596.65) v1@7491.41,1587.26 ; v1(7503.52,2026.37) 7503.67,2026.37 7520,2042.71 C234.1@7520,2069.33 ; v1@7503.52,2031.87 ccw(c7503.52,2045.5) 7513.16,2035.86 ; v1@7509.02,2026.37 cw(c7521.96,2026.37) 7512.81,2035.52 ; C220.1@7515.89,1615.22 cw(c7505.97,1605.3) 7520,1605.3 cw(c7534.03,1605.3) C220.1@7524.11,1615.22 ; C234.1@7515.89,2065.22 cw(c7505.97,2055.3) 7520,2055.3 cw(c7534.03,2055.3) C234.1@7524.11,2065.22 ; C218.1@7515.89,2215.22 cw(c7505.97,2205.3) 7520,2205.3 cw(c7534.03,2205.3) C218.1@7524.11,2215.22 ; v1@7515.97,2174.26 ccw(c7506.23,2184) 7520,2184 ; v1(7519.86,2170.37) 7520,2170.52 C218.1@7520,2219.33 ; C236.1@7520,1469.33 7563.48,1469.33 7584.15,1490 C203.1@7667.01,1490 7667.01,1433.37 ; C220.1@7520,1619.33 7520,1590 7513.37,1583.37 v1@7489.19,1583.37 ; 7520,2183.31 ccw(c7532.79,2183.31) v1@7523.75,2174.26 ; C236.1@7524.11,1465.22 cw(c7534.03,1455.3) 7534.03,1469.33 cw(c7534.03,1483.36) C236.1@7524.11,1473.44 ; R156.2@7526.24,3814.55 cw(c7517.16,3805.46) 7530,3805.46 cw(c7542.84,3805.47) R156.2@7533.76,3814.55 ; R235.2@7530,3453.66 7568.9,3453.66 7571.57,3456.33 7571.57,3456.42 v1(7576.86,3461.71) ; R156.2@7530,3818.31 7530,3769.9 7530.19,3769.71 7550,3769.71 7555.19,3769.71 7554.9,3770 v1(7550,3770) ; C60.1@7530.89,4285.22 cw(c7520.97,4275.3) 7535,4275.3 cw(c7549.03,4275.3) C60.1@7539.11,4285.22 ; R235.2@7534.25,3449.9 cw(c7543.33,3440.82) 7543.33,3453.66 cw(c7543.33,3466.51) R235.2@7534.25,3457.43 ; C60.1@7535,4289.33 7535,4265.04 7539.33,4260.71 7539.52,4260.71 v1(7576.52,4223.71) ; C59.1@7535,4444.33 7564.19,4473.52 v1(7564.19,4601.71) 7558.52,4601.71 7556.86,4600.04 7556.86,4592.66 ; C59.1@7535,4450.14 ccw(c7535,4464.17) 7544.92,4454.25 ccw(c7554.84,4444.33) C59.1@7540.81,4444.33 ; C58.1@7535,4584.33 7548.52,4584.33 ; 7536.02,3769.71 ccw(c7536.02,3783.98) v1@7546.11,3773.89 ; 7537.43,3769.71 cw(c7537.43,3757.43) v1@7546.11,3766.11 ; C58.1@7537.59,4589.53 ccw(c7545.05,4604.47) 7556.86,4592.66 ; C58.1@7539.22,4580.33 cw(c7548.52,4571.5) 7548.52,4584.33 ; C58.1@7539.22,4588.33 ccw(c7548.52,4597.16) 7548.52,4584.33 ; 7544.16,3453.66 ccw(c7544.16,3494.4) v1@7572.97,3465.6 ; 7553.59,4589.4 ccw(c7541.28,4601.71) v1@7558.69,4601.71 ; U47.11@7555.59,3050.75 7618.56,3050.75 7619.86,3049.45 7619.86,3049.37 v1(7631.86,3037.37) ; v1@7560.3,4597.82 cw(c7550.91,4588.43) 7564.19,4588.43 cw(c7577.47,4588.43) v1@7568.08,4597.82 ; v1@7571.02,4223.71 ccw(c7557.75,4223.71) 7567.14,4233.1 ccw(c7576.52,4242.49) v1@7576.52,4229.21 ; v1@7641.17,4860.24 ccw(c7658.5,4869.79) 7658.5,4850 ; C203.1@7643.41,1466.4 ccw(c7586.45,1409.44) 7586.45,1490 ccw(c7586.44,1570.56) C203.1@7643.41,1513.6 ; v1(7646.86,4863.37) 7646.86,4853.37 7650.23,4850 R159.2@7678.82,4850 cw(c7678.82,4881) v1@7651.67,4866.03 ; C203.1@7651.9,1474.89 ccw(c7615.42,1438.41) 7615.42,1490 ccw(c7615.42,1541.59) C203.1@7651.9,1505.11 ; C203.1@7652.75,1455.89 cw(c7642.1,1433.38) 7667.01,1433.38 ; C200.1@7667.01,1655 v1@7721.52,1655 ; v1@7669.64,1407.26 ccw(c7660.25,1416.65) 7673.52,1416.65 ccw(c7686.8,1416.65) v1@7677.41,1407.26 ; v4@7669.71,5917.89 cw(c7659.79,5907.97) 7673.82,5907.97 cw(c7687.85,5907.97) v4@7677.93,5917.89 ; v4@7669.71,5926.11 ccw(c7659.79,5936.03) 7673.82,5936.03 ccw(c7687.85,5936.03) v4@7677.93,5926.11 ; R282.1@7670.06,5900.59 ccw(c7660.98,5909.67) 7673.82,5909.67 ccw(c7686.66,5909.67) R282.1@7677.58,5900.59 ; R280.1@7670.06,5942.41 cw(c7660.98,5933.33) 7673.82,5933.33 cw(c7686.66,5933.33) R280.1@7677.58,5942.41 ; v1(7673.52,1403.37) 7673.52,1426.86 7667.01,1433.37 ; R282.1@7673.82,5896.33 v4(7673.82,5922) R280.1@7673.82,5946.67 ; R159.2@7675.06,4846.24 ccw(c7665.98,4837.16) 7665.98,4850 ccw(c7665.98,4862.84) R159.2@7675.06,4853.76 ; C203.1@7681.27,1455.89 ccw(c7691.91,1433.38) 7667.01,1433.38 ; C200.1@7696.73,1639.82 cw(c7721.52,1627.16) v1@7721.52,1655 ; C200.1@7696.73,1670.18 ccw(c7721.52,1682.84) v1@7721.52,1655 ; C200.1@7705.79,1655 ccw(c7705.79,1674.11) v1@7719.3,1660.6 ; v1@7721.86,1655.33 v1@7721.52,1655 ; v1@7721.86,1655.37 v1(7723.19,1656.71) ; v2@7763.52,4366.71 v2@7764.86,4368.04 ; v2@7764.52,4368.37 v2@7764.86,4368.04 ; v2(7771.26,4366.89) 7769.78,4368.37 7765.19,4368.37 v2@7764.86,4368.04 ; LED2.1@7826.24,2164.43 cw(c7855.89,2166.07) 7834.89,2187.07 ; LED2.1@7829.69,2176.85 ccw(c7822.82,2188.72) 7836.54,2188.72 ; LED2.1@7836.54,2165 7836.54,2188.72 ; LED2.1@7838.22,2165.09 cw(c7891.86,2168.06) 7853.87,2206.06 ; LED2.1@7843.38,2176.85 cw(c7850.25,2188.72) 7836.54,2188.72 ; LED2.1@7850.2,2165.76 cw(c7927.84,2170.06) v1(7872.86,2225.04) 7836.54,2188.72 ; v1@7867.36,2225.04 cw(c7854.08,2225.04) 7863.47,2215.65 cw(c7872.86,2206.26) v1@7872.86,2219.54 ; U2.3@7874.17,3831.34 7927.19,3831.34 7932.19,3826.34 7932.19,3758.71 v1(7931.86,3758.37) ; U2.3@7901.33,3825.84 cw(c7914.61,3812.56) 7914.61,3831.34 cw(c7914.61,3850.12) U2.3@7901.33,3836.84 ; v4@7901.7,5917.89 cw(c7891.78,5907.97) 7905.81,5907.97 cw(c7919.84,5907.97) v4@7909.92,5917.89 ; v4@7901.7,5926.11 ccw(c7891.78,5936.03) 7905.81,5936.03 ccw(c7919.84,5936.03) v4@7909.92,5926.11 ; R281.1@7902.05,5900.59 ccw(c7892.97,5909.67) 7905.81,5909.67 ccw(c7918.65,5909.67) R281.1@7909.57,5900.59 ; R279.1@7902.05,5942.41 cw(c7892.97,5933.33) 7905.81,5933.33 cw(c7918.65,5933.33) R279.1@7909.57,5942.41 ; R281.1@7905.81,5896.33 v4(7905.81,5922) R279.1@7905.81,5946.67 ; v1(7906.86,3416.71) 7947.52,3457.37 7947.52,3479.5 7947.32,3479.5 C35.1@7947.32,3525 ; v1@7906.86,3422.21 ccw(c7906.86,3435.49) 7916.25,3426.1 ccw(c7925.64,3416.71) v1@7912.36,3416.71 ; v1@7927.97,3762.26 ccw(c7917.78,3772.46) 7932.19,3772.46 ; 7932.19,3770.85 ccw(c7944.33,3770.85) v1@7935.75,3762.26 ; v1@7936.3,3002.93 ccw(c7926.91,3012.32) 7940.19,3012.32 ccw(c7953.47,3012.32) v1@7944.08,3002.93 ; v1(7940.19,2999.04) 7940.19,3015.37 7944.07,3019.25 U47.33@8004.41,3019.25 8075.08,3019.25 C153.1@8080,3014.33 8096.9,3014.33 v1(8111.19,3000.04) ; C35.1@7943.21,3520.89 cw(c7933.29,3510.97) 7947.32,3510.97 cw(c7961.35,3510.97) C35.1@7951.43,3520.89 ; v1@8023.64,3878.35 cw(c8014.25,3868.96) 8027.52,3868.96 cw(c8040.8,3868.96) v1@8031.41,3878.35 ; v1@8027.52,3882.04 8027.52,3796.3 8042.49,3781.34 U2.13@8098.58,3781.34 ; U23.4@8049,2423.2 8049,2464 8050.19,2465.19 v1(8050.19,2485.04) ; 8054.09,3019.25 cw(c8054.09,2988.42) C153.1@8075.89,3010.22 ; v1(8065,3255) 8120,3255 8125,3250 C36.1@8125,3192.01 ; v1@8068.89,3251.11 cw(c8078.28,3241.72) 8078.28,3255 cw(c8078.28,3268.28) v1@8068.89,3258.89 ; U2.13@8071.43,3775.84 ccw(c8058.15,3762.56) 8058.15,3781.34 ccw(c8058.15,3800.12) U2.13@8071.43,3786.84 ; C153.1@8077.07,3019.78 cw(c8083.83,3007.2) 8093.93,3017.3 ; C154.1@8080,2919.33 8125.67,2919.33 8139.9,2905.1 v1@8140,2905 ; C153.1@8080,3020.52 cw(c8080,2994.66) 8098.29,3012.95 ; C153.1@8082.75,3009.21 cw(c8091.81,2992.34) v1@8105.35,3005.88 ; C154.1@8084.11,2915.22 cw(c8094.03,2905.3) 8094.03,2919.33 cw(c8094.03,2933.36) C154.1@8084.11,2923.44 ; C153.1@8084.11,3010.22 cw(c8094.03,3000.3) 8094.03,3014.33 cw(c8094.03,3028.36) C153.1@8084.11,3018.44 ; C36.1@8108.23,3220.86 ccw(c8091.3,3250) 8125,3250 ccw(c8158.7,3250) C36.1@8141.77,3220.86 ; v4@8160.89,4259.11 ccw(c8150.97,4269.03) 8165,4269.03 ccw(c8179.03,4269.03) v4@8169.11,4259.11 ; C57.1@8160.89,4280.22 cw(c8150.97,4270.3) 8165,4270.3 cw(c8179.03,4270.3) C57.1@8169.11,4280.22 ; C56.1@8160.89,4499.78 ccw(c8150.97,4509.7) 8165,4509.7 ccw(c8179.03,4509.7) C56.1@8169.11,4499.78 ; v4@8160.89,4530.89 cw(c8150.97,4520.97) 8165,4520.97 cw(c8179.03,4520.97) v4@8169.11,4530.89 ; C55.1@8160.89,4634.78 ccw(c8150.97,4644.7) 8165,4644.7 ccw(c8179.03,4644.7) C55.1@8169.11,4634.78 ; v4@8160.89,4655.89 cw(c8150.97,4645.97) 8165,4645.97 cw(c8179.03,4645.97) v4@8169.11,4655.89 ; v4(8165,4255) C57.1@8165,4284.33 ; C56.1@8165,4495.67 v4(8165,4535) ; C55.1@8165,4630.67 v4(8165,4660) ; 5550,2764.42 5551.86,2766.27 v1(5551.86,2782.04) 5551.86,2861.71 5590.19,2900.04 5715.19,2900.04 5738.02,2877.21 ; 5550,2764.42 U61.104@5516.83,2764.42 5550,2764.42 ; 5715.19,3208.37 5751.19,3208.37 5750,3207.18 ; 5738.02,2877.21 5777.52,2916.71 5781.71,2916.71 5828.52,2963.52 ; U53.8@5930.59,1580.59 5940,1590 v1@5940,1630.04 ; v1@5940.19,1696.04 5938.19,1698.04 5936.19,1700.04 v1(5940.19,1700.04) v1@5940.19,1696.04 ; v1(6198.52,4208.37) 6198.52,4175.37 6199.45,4174.45 ; v1(6198.52,4208.37) 6199.45,4207.45 6199.45,4174.45 ; 6470,1530 v1(6470,1555) ; 7130.54,2258.69 7128.11,2258.69 7128.11,2257.37 7131.86,2257.37 7130.54,2258.69 ; 7215.19,2421.71 7233.52,2440.04 ; 7215.19,2421.71 7233.52,2440.04 ; 7233.52,2440.04 v1@7242.76,2449.28 ; 7233.52,2440.04 v1@7242.76,2449.28 ; 7240.8,2447.32 cw(c7250.19,2437.93) 7250.19,2451.21 ccw(c7250.19,2437.93) 7240.8,2447.32 ; 7240.8,2447.32 ccw(c7231.41,2456.71) 7244.69,2456.71 cw(c7231.41,2456.71) 7240.8,2447.32 ; v1@7242.76,2449.28 v1(7250.19,2456.71) ; v1@7242.76,2449.28 v1(7250.19,2456.71) ; v1(7250.19,2456.71) 7277.01,2483.52 ; 7385,3999.86 7385,3936.37 7385.67,3935.71 7385.86,3935.71 7385.86,3928.71 7456.86,3857.71 7456.86,3841.71 ; 7398.52,3678.11 7406.86,3686.44 ; 7406.86,3686.44 7406.86,3728.71 7438.52,3760.37 7438.52,3813.48 ; 7438.52,3813.48 7456.86,3831.82 7456.86,3841.71 ; v1@7489.19,1583.37 7489.19,1581.71 v1(7487.52,1583.37) v1@7489.19,1583.37 ; 7548.52,4584.33 7556.86,4592.66 ; R234.2@1140.06,3164.25 ccw(c1128.13,3176.18) 1145,3176.18 cw(c1128.13,3176.18) R234.2@1140.06,3164.25
  MidLayer1 w4: v1(4637.88,4216.78) 4640.37,4216.78 4662.86,4194.29 4704.29,4194.29 4733.04,4165.54 4767.65,4165.54 4773.69,4159.5 4798.07,4135.12 4855.26,4135.12 4860,4135.12 4870,4135.12 4918.62,4135.12 5012.16,4135.12 ccw(c5012.16,4149.17) 5022.09,4139.24 ; v1@4713.47,4471.66 cw(c4697.26,4455.44) 4720.19,4455.44 cw(c4743.13,4455.44) v1@4726.91,4471.66 ; v1@4716.3,4474.49 cw(c4706.91,4465.1) 4720.19,4465.1 cw(c4733.47,4465.1) v1@4724.08,4474.49 ; v1(4720.19,4478.37) 4720.19,4453.37 4731.84,4441.73 4855.26,4441.73 4860,4441.73 4870,4441.73 4918.62,4441.73 5012.16,4441.73 cw(c5012.16,4427.68) 5022.09,4437.61 ; v1(4757.52,3924.04) 4771.76,3938.27 4860,3938.27 4870,3938.27 4918.62,3938.27 5012.16,3938.27 ccw(c5012.16,3952.32) 5022.09,3942.39 ; 4870,4323.62 4918.62,4323.62 5012.16,4323.62 cw(c5012.16,4309.57) 5022.09,4319.5 ; v3@5028.2,3954.43 cw(c5010.16,3956.01) 5021.8,3942.14 cw(c5033.44,3928.27) v3@5035.02,3946.31 ; v3@5028.2,4151.28 cw(c5010.16,4152.86) 5021.8,4138.99 cw(c5033.44,4125.12) v3@5035.02,4143.16 ; v3@5028.2,4307.46 ccw(c5010.16,4305.88) 5021.8,4319.75 ccw(c5033.44,4333.62) v3@5035.02,4315.58 ; v3@5028.2,4425.57 ccw(c5010.16,4423.99) 5021.8,4437.86 ccw(c5033.44,4451.73) v3@5035.02,4433.69 ; v1@5115.02,3520.71 ccw(c5092.09,3520.71) 5108.31,3536.92 ccw(c5124.52,3553.14) v1@5124.52,3530.21 ; v1@5119.02,3520.71 ccw(c5105.75,3520.71) 5115.13,3530.1 ccw(c5124.52,3539.49) v1@5124.52,3526.21 ; v1(5124.52,3520.71) 5104.19,3541.04 5104.19,3563.04 5138.27,3597.12 5138.27,3660 5138.27,3670 5138.27,3718.62 5138.27,3812.16 cw(c5152.32,3812.16) 5142.39,3822.09 ; 5138.27,3643.37 5138.27,3655.26 ; 5142.39,4557.91 cw(c5152.32,4567.84) 5138.27,4567.84 5138.27,4661.38 5138.27,4710 5138.27,4720 5138.27,4724.74 5138.27,4873.12 v1(5149.52,4884.37) ; v3@5146.31,3835.02 cw(c5128.27,3833.44) 5142.14,3821.8 cw(c5156.01,3810.16) v3@5154.43,3828.2 ; v3@5146.31,4544.98 ccw(c5128.27,4546.56) 5142.14,4558.2 ccw(c5156.01,4569.84) v3@5154.43,4551.8 ; v1@5248.81,3552.09 ccw(c5230.52,3570.38) 5256.38,3570.38 ; v1@5251.64,3549.26 ccw(c5240.17,3560.72) 5256.38,3560.72 ; v1@5256.38,3546.23 5256.38,3655.26 5256.38,3660 5256.38,3670 5256.38,3718.62 5256.38,3812.16 cw(c5270.43,3812.16) 5260.5,3822.09 ; 5256.38,3566.24 ccw(c5276.39,3566.24) v1@5262.24,3552.09 ; v3@5264.42,3835.02 cw(c5246.38,3833.44) 5260.25,3821.8 cw(c5274.12,3810.16) v3@5272.54,3828.2 ; v1@5329.95,4825.78 cw(c5317.47,4813.3) 5335.12,4813.3 ; 5335.12,4581.77 5335.12,4567.84 ; 5335.12,4805.83 cw(c5363.34,4805.83) v1@5343.39,4825.78 ; 5335.12,4815.49 cw(c5353.68,4815.49) v1@5340.56,4828.61 ; 5339.24,4557.91 cw(c5349.17,4567.84) 5335.12,4567.84 ; v1@5339.52,4833.37 5337.54,4833.37 v1(5336.67,4832.5) 5335.12,4830.95 5335.12,4724.74 5335.12,4720 5335.12,4710 5335.12,4567.84 ; v3@5343.16,4544.98 ccw(c5325.12,4546.56) 5338.99,4558.2 ccw(c5352.86,4569.84) v3@5351.28,4551.8 ; v3@5428.72,3828.2 cw(c5427.14,3810.16) 5441.01,3821.8 cw(c5454.88,3833.44) v3@5436.84,3835.02 ; v1@5429.22,3625.14 ccw(c5398.26,3660) 5444.88,3660 ; v1@5431.87,3622.15 ccw(c5406.17,3651.1) 5444.88,3651.1 ; v1@5434.53,3619.16 ccw(c5414.07,3642.19) 5444.88,3642.19 ; v1(5435.52,3618.04) 5444.88,3627.39 5444.88,3660 5444.88,3670 5444.88,3812.16 ; v1@5437.18,3616.17 ccw(c5421.98,3633.29) 5444.88,3633.29 ; 5440.76,3822.09 cw(c5430.83,3812.16) 5444.88,3812.16 ; 5444.88,3798.23 5444.88,3812.16 ; v3@5507.46,4551.8 ccw(c5505.88,4569.84) 5519.75,4558.2 ccw(c5533.62,4546.56) v3@5515.58,4544.98 ; 5519.5,4557.91 ccw(c5509.57,4567.84) 5523.62,4567.84 5523.62,4661.38 5523.62,4710 5523.62,4720 5523.62,4724.74 ; v1@5523.52,4793.04 v1@5523.62,4793.13 ; 5523.62,4725.04 v1@5523.62,4793.13 ; v3@5625.57,3828.2 cw(c5623.99,3810.16) 5637.86,3821.8 cw(c5651.73,3833.44) v3@5633.69,3835.02 ; v3@5625.57,4551.8 ccw(c5623.99,4569.84) 5637.86,4558.2 ccw(c5651.73,4546.56) v3@5633.69,4544.98 ; 5637.61,3822.09 cw(c5627.68,3812.16) 5641.73,3812.16 5641.73,3718.62 5641.73,3670 5641.73,3660 5641.73,3655.26 ; 5637.61,4557.91 ccw(c5627.68,4567.84) 5641.73,4567.84 5641.73,4661.38 5641.73,4710 ; 5641.73,3658.37 5641.73,3521.5 v1(5647.19,3516.04) ; v3@5744.98,3946.31 cw(c5746.56,3928.27) 5758.2,3942.14 cw(c5769.84,3956.01) v3@5751.8,3954.43 ; v3@5744.98,4064.42 cw(c5746.56,4046.38) 5758.2,4060.25 cw(c5769.84,4074.12) v3@5751.8,4072.54 ; v3@5744.98,4236.84 ccw(c5746.56,4254.88) 5758.2,4241.01 ccw(c5769.84,4227.14) v3@5751.8,4228.72 ; v3@5744.98,4433.69 ccw(c5746.56,4451.73) 5758.2,4437.86 ccw(c5769.84,4423.99) v3@5751.8,4425.57 ; 5757.91,3942.39 ccw(c5767.84,3952.32) 5767.84,3938.27 5861.38,3938.27 5910,3938.27 ; 5757.91,4060.5 ccw(c5767.84,4070.43) 5767.84,4056.38 5861.38,4056.38 5910,4056.38 ; 5757.91,4240.76 cw(c5767.84,4230.83) 5767.84,4244.88 5861.38,4244.88 5910,4244.88 5920,4244.88 5955.12,4244.88 5980,4220 ; 5757.91,4437.61 cw(c5767.84,4427.68) 5767.84,4441.73 5861.38,4441.73 5910,4441.73 ; v1@5523.62,4793.14 v1(5528.86,4798.37) v1@5523.62,4793.13
  MidLayer1 w12: J8.12@2553.71,6612.26 ccw(c2509.51,6568.06) 2509.51,6630.56 ccw(c2509.51,6693.07) J8.12@2553.71,6648.87 ; J8.12@2562.19,6620.74 ccw(c2538.48,6597.03) 2538.48,6630.56 ccw(c2538.48,6664.09) J8.12@2562.19,6640.38 ; J8.12@2572.02,6630.56 2500.56,6630.56 2455,6585 2455,6410 2760,6105 2840,6105 2940,6005 2940,5840 2928,5828 v1(2789.7,5828) ; v1@2793.59,5824.11 cw(c2802.98,5814.72) 2802.98,5828 cw(c2802.98,5841.28) v1@2793.59,5831.89 ; v1@5899.67,4741.37 v1@5900,4741.71 ; 5973.52,4216.71 6019.52,4216.71 v1(6030.52,4227.71) ; 5990.69,4216.71 ccw(c5990.69,4267.54) v1@6026.64,4231.6 ; 6019.66,4216.71 ccw(c6019.66,4238.57) v1@6035.12,4223.11 ; v1@6906.86,3711.37 v1(6915.19,3711.37) ; v1(7246.19,4655.71) v1@7248.52,4658.04 ; v1(7550,3770) 7554.9,3770 7555.19,3769.71 v1@7555.19,3770
  MidLayer2 w4: v1@4713.47,4471.66 cw(c4697.26,4455.44) 4720.19,4455.44 cw(c4743.13,4455.44) v1@4726.91,4471.66 ; v1@4716.3,4474.49 cw(c4706.91,4465.1) 4720.19,4465.1 cw(c4733.47,4465.1) v1@4724.08,4474.49 ; v1(4720.19,4478.37) 4720.19,4428.37 4798.52,4350.04 4813.51,4350.04 4831.58,4331.97 4860,4331.97 4870,4331.97 4997.36,4331.97 5016.78,4331.97 5090.9,4331.97 5110.4,4331.97 cw(c5110.4,4290.24) 5139.91,4319.75 ; 4870,4048.03 4997.36,4048.03 5016.78,4048.03 5090.9,4048.03 5110.4,4048.03 ccw(c5110.4,4089.76) 5139.91,4060.25 ; 5105.19,3616.71 5198.52,3616.71 ; v1@5142.81,4877.66 cw(c5126.59,4861.44) 5149.52,4861.44 cw(c5172.46,4861.44) v1@5156.24,4877.66 ; v1@5145.64,4880.49 cw(c5136.25,4871.1) 5149.52,4871.1 cw(c5162.8,4871.1) v1@5153.41,4880.49 ; v3@5146.31,4072.54 cw(c5128.27,4074.12) 5139.91,4060.25 ; v3@5146.31,4307.46 ccw(c5128.27,4305.88) 5139.91,4319.75 ; v1(5149.52,4884.37) 5149.52,4841.71 5182.86,4808.37 5209.19,4808.37 5261.86,4755.71 ; v3@5153.13,4064.42 ccw(c5151.55,4046.38) 5139.91,4060.25 ; v3@5153.13,4315.58 cw(c5151.55,4333.62) 5139.91,4319.75 ; v1@5246.02,3545.37 ccw(c5223.09,3545.37) 5239.31,3561.59 ccw(c5255.52,3577.81) v1@5255.52,3554.87 ; 5248.03,3655.26 5248.03,3658.37 ; v1@5250.02,3545.37 ccw(c5236.75,3545.37) 5246.14,3554.76 ccw(c5255.52,3564.15) v1@5255.52,3550.87 ; v1(5255.52,3545.37) 5198.52,3602.37 5198.52,3616.71 ; v3@5264.42,3953.13 cw(c5246.38,3951.55) 5260.25,3939.91 ; v3@5264.42,4426.87 ccw(c5246.38,4428.45) 5260.25,4440.09 ; v3@5272.54,3946.31 ccw(c5274.12,3928.27) 5260.25,3939.91 ; v3@5272.54,4433.69 cw(c5274.12,4451.73) 5260.25,4440.09 ; 5319.05,4812.9 ccw(c5299.45,4832.5) v1@5327.17,4832.5 ; 5323.83,4817.68 cw(c5336.67,4804.84) v1@5336.67,4823 ; 5325.88,4819.73 ccw(c5313.11,4832.5) v1@5331.17,4832.5 ; v1(5336.67,4832.5) 5337.54,4833.37 5339.52,4833.37 5261.86,4755.71 ; v3@5507.46,3946.31 cw(c5505.88,3928.27) 5519.75,3939.91 ; v3@5507.46,4433.69 ccw(c5505.88,4451.73) 5519.75,4440.09 ; v3@5515.58,3953.13 ccw(c5533.62,3951.55) 5519.75,3939.91 ; v3@5515.58,4426.87 cw(c5533.62,4428.45) 5519.75,4440.09 ; v1@5522.14,4791.66 cw(c5498.4,4767.92) 5531.97,4767.92 ; v1@5524.97,4794.49 cw(c5508.06,4777.57) 5531.97,4777.57 ; v1@5527.8,4797.31 cw(c5517.71,4787.23) 5531.97,4787.23 ; v1(5528.86,4798.37) 5531.97,4795.26 5531.97,4724.74 5531.97,4720 5531.97,4710 5531.97,4582.64 5531.97,4563.22 5531.97,4489.1 5531.97,4469.6 cw(c5490.24,4469.6) 5519.75,4440.09 ; 5531.97,4782.96 cw(c5544.27,4782.96) v1@5535.57,4791.66 ; 5569.86,3599.04 5565.19,3603.71 5565.19,3619.02 5551.12,3633.1 5531.97,3652.24 5531.97,3660 5531.97,3670 5531.97,3797.36 5531.97,3816.78 5531.97,3890.9 5531.97,3910.4 ccw(c5490.24,3910.4) 5519.75,3939.91 ; v3@5626.87,4064.42 cw(c5628.45,4046.38) 5640.09,4060.25 ; v3@5626.87,4315.58 ccw(c5628.45,4333.62) 5640.09,4319.75 ; v3@5633.69,4072.54 ccw(c5651.73,4074.12) 5640.09,4060.25 ; v3@5633.69,4307.46 cw(c5651.73,4305.88) 5640.09,4319.75 ; 5910,4048.03 5782.64,4048.03 5763.22,4048.03 5689.1,4048.03 5669.6,4048.03 cw(c5669.6,4089.76) 5640.09,4060.25 ; v1@6019.02,4361.71 cw(c5996.09,4361.71) 6012.31,4345.49 cw(c6028.52,4329.27) v1@6028.52,4352.21 ; v1@6023.02,4361.71 cw(c6009.75,4361.71) 6019.14,4352.32 cw(c6028.52,4342.93) v1@6028.52,4356.21 ; v1(6028.52,4361.71) 5998.79,4331.97 5920,4331.97 5910,4331.97 5782.64,4331.97 5763.22,4331.97 5689.1,4331.97 5669.6,4331.97 ccw(c5669.6,4290.24) 5640.09,4319.75 ; 5198.52,3616.71 5221.71,3616.71 5248.03,3643.03 5248.03,3658.37 ; 5248.03,3658.37 5248.03,3660 5248.03,3670 5248.03,3797.36 5248.03,3816.78 5248.03,3890.9 5248.03,3910.4 cw(c5289.76,3910.4) 5260.25,3939.91 ; 5260.25,4440.09 cw(c5289.76,4469.6) 5248.03,4469.6 5248.03,4489.1 5248.03,4563.22 5248.03,4582.64 5248.03,4710 5248.03,4720 5248.03,4724.74 5248.03,4741.88 5261.86,4755.71
  MidLayer2 w12: v4(4935,465) 4935,446.97 4954.16,427.81 4963.33,427.81 5041.14,350 5090,350 5203.97,350 5262.86,291.11 v1(5262.86,233.37) ; v1(4955,4850) 4955.56,4850 v1@4959.52,4846.04 ; v1(5023.52,3558.37) 5023.52,3566.71 5078.86,3622.04 5099.86,3622.04 5105.19,3616.71 ; v1@5029.02,3558.37 cw(c5062.42,3558.37) 5038.81,3581.99 ; v1@5258.97,237.26 ccw(c5249.58,246.65) 5262.86,246.65 ccw(c5276.14,246.65) v1@5266.75,237.26 ; 5569.86,3599.04 5585.52,3583.37 5607.86,3583.37 5647.19,3544.04 v1(5647.19,3516.04) ; v1@5643.3,3519.93 ccw(c5633.91,3529.32) 5647.19,3529.32 ccw(c5660.47,3529.32) v1@5651.08,3519.93 ; v1(6389.52,2315.37) v1@6390.19,2315.37 ; v1(6905.19,3916.71) v1@6913.52,3916.71 ; v1(7180,6070) 7180,5985 7263,5902 7454,5902 7480,5876 7509,5876 7520,5887 7638.82,5887 v4(7673.82,5922) v4(7905.81,5922) v4@7907,5922 ; v1(7283.86,544.37) v1@7286.52,541.71 ; v1@7600,440.23 v1(7600,445) ; v5@7606.86,641.73 v5@7606.86,642.71 ; v4@7668.01,5922 cw(c7653.98,5922) 7663.9,5912.08 cw(c7673.82,5902.16) v4@7673.82,5916.19 ; v4@7677.93,5917.89 cw(c7687.85,5907.97) 7687.85,5922 cw(c7687.85,5936.03) v4@7677.93,5926.11 ; v4@7901.7,5917.89 ccw(c7891.78,5907.97) 7891.78,5922 ccw(c7891.78,5936.03) v4@7901.7,5926.11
